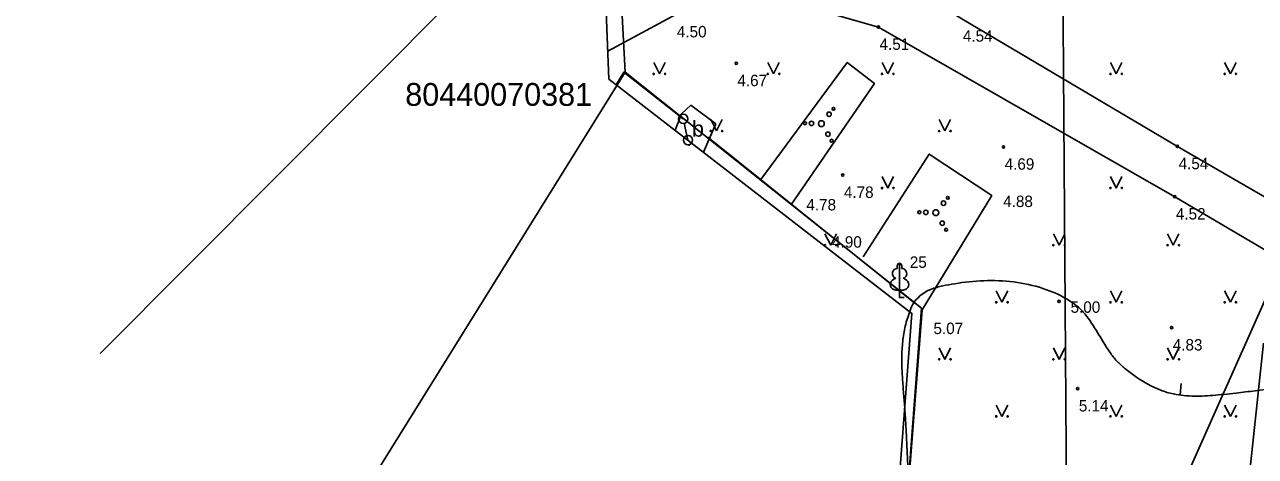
# Model space of a CAD drawing. Extents: x 519536 to 519949, y 326041 to 326519.
# Drawn here: x 519637.2 to 519691.1, y 326168.2 to 326187.2 of the extents above; entities that cross this region are included whole.
import ezdxf

# ---------------------------------------------------------------- set-up
doc = ezdxf.new("R2010")
doc.units = 0
for name, color, linetype in [('CELI_CMAL_####_####_#', 7, 'Continuous'), ('CELI_CSEG_####_TKST_#', 7, 'Continuous'), ('ELEK_VADP_VSPR_####_#', 7, 'Continuous'), ('ELEK_VADV_ZSPR_####_#', 7, 'Continuous'), ('NORB_ELEM_####_####_#', 7, 'Continuous'), ('NORB_ZOGS_BARJ_####_#', 7, 'Continuous'), ('NORB_ZOGS_KBST_####_#', 7, 'Continuous'), ('NORB_ZOGS_ZSTP_####_#', 7, 'Continuous'), ('RAMI_UZMR_####_####_#', 7, 'Continuous'), ('RELJ_AATZ_####_TKST_#', 7, 'Continuous'), ('RELJ_ELEM_####_####_#', 7, 'Continuous'), ('RELJ_HORZ_PAMT_####_#', 7, 'Continuous'), ('ROBZ_UZMR_####_####_#', 7, 'Continuous'), ('ROBZ_UZMR_####_TKST_#', 7, 'Continuous'), ('SILT_VADP_UDEN_####_#', 7, 'Continuous'), ('TERT_DIAM_####_TKST_#', 7, 'Continuous'), ('TERT_ELEM_####_####_#', 7, 'Continuous'), ('TERT_KONT_####_####_#', 7, 'Continuous')]:
    doc.layers.add(name, color=color, linetype=linetype)

msp = doc.modelspace()

# ---------------------------------------------------------------- linework, layer by layer
at = {"layer": 'CELI_CMAL_####_####_#'}
for points in [[(519725.6, 326145.595), (519722.795, 326148.479), (519717.487, 326152.615), (519712.383, 326157.466), (519706.872, 326166.697), (519703.889, 326170.776), (519699.04, 326175.245), (519687.684, 326181.825), (519678.238, 326187.413), (519670.804, 326192.027), (519670.048, 326192.682), (519664.865, 326189.411), (519662.65, 326188.197)], [(519662.737, 326185.995), (519665.714, 326187.6), (519670.496, 326188.216), (519674.588, 326187.052), (519687.563, 326179.623), (519697.361, 326173.852), (519702.298, 326169.28), (519707.151, 326162.302), (519711.634, 326155.197), (519719.91, 326147.956), (519722.688, 326145.028)], [(519665.692, 326182.539), (519665.97, 326183.253)], [(519666.933, 326181.568), (519667.468, 326182.81), (519666.379, 326183.628), (519665.97, 326183.253)], [(519665.688, 326182.529), (519665.692, 326182.539)], [(519666.932, 326181.567), (519666.933, 326181.568)]]:
    msp.add_lwpolyline(points, dxfattribs=at)
at = {"layer": 'ELEK_VADP_VSPR_####_#'}
msp.add_lwpolyline([(519683.028, 326137.518), (519682.623, 326195.513)], dxfattribs=at)
at = {"layer": 'ELEK_VADV_ZSPR_####_#'}
msp.add_line((519666.72, 326119.401), (519722.531, 326244.78), dxfattribs=at)
at = {"layer": 'NORB_ELEM_####_####_#'}
for centre in [(519666.043, 326183.032), (519666.251, 326182.101)]:
    msp.add_circle(centre, 0.202, dxfattribs=at)
at = {"layer": 'NORB_ZOGS_BARJ_####_#'}
for p, q in [((519666.087, 326182.837), (519666.251, 326182.101)), ((519666.295, 326181.906), (519666.309, 326181.844))]:
    msp.add_line(p, q, dxfattribs=at)
at = {"layer": 'NORB_ZOGS_KBST_####_#'}
msp.add_line((519676.196, 326174.948), (519667.128, 326182.232), dxfattribs=at)
for points in [[(519666.043, 326183.032), (519663.443, 326185.082), (519663.124, 326184.549)], [(519663.124, 326184.549), (519663.108, 326184.523)]]:
    msp.add_lwpolyline(points, dxfattribs=at)
at = {"layer": 'NORB_ZOGS_ZSTP_####_#'}
msp.add_lwpolyline([(519659.694, 326134.606), (519659.86, 326134.591), (519673.328, 326133.453), (519674.978, 326154.964), (519676.5, 326174.67)], dxfattribs=at)
at = {"layer": 'RAMI_UZMR_####_####_#'}
msp.add_lwpolyline([(519720.513, 326144.604), (519669.064, 326119.018), (519667.491, 326117.773), (519659.343, 326134.977), (519672.997, 326134.231), (519676.059, 326174.512), (519662.786, 326184.772), (519662.359, 326195.553), (519640.272, 326217.733), (519626.848, 326230.605), (519625.448, 326232.202), (519636.536, 326238.028), (519608.178, 326320.927), (519604.881, 326332.267), (519606.632, 326340.411), (519606.503, 326354.123), (519598.183, 326371.842)], dxfattribs=at)
at = {"layer": 'RELJ_ELEM_####_####_#'}
for centre in [(519674.588, 326187.052), (519668.364, 326185.462), (519680.066, 326181.804), (519687.684, 326181.825), (519673.028, 326180.569), (519687.563, 326179.623), (519682.503, 326175.038), (519687.427, 326173.886), (519683.315, 326171.219)]:
    msp.add_circle(centre, 0.05, dxfattribs=at)
at = {"layer": 'RELJ_HORZ_PAMT_####_#'}
msp.add_line((519687.8, 326170.946), (519687.851, 326171.443), dxfattribs=at)
for points in [[(519679.571, 326197.325), (519680.165, 326196.852), (519680.813, 326196.657), (519682.865, 326196.481), (519684.919, 326196.331), (519689.028, 326196.07), (519690.241, 326196.004), (519691.17, 326195.809), (519691.617, 326195.63), (519692.053, 326195.411), (519692.478, 326195.145), (519692.871, 326194.841), (519693.625, 326194.147), (519694.626, 326192.899), (519695.352, 326191.531), (519696.758, 326187.942), (519697.617, 326185.639), (519698.149, 326184.524), (519698.492, 326183.987), (519698.688, 326183.726), (519698.904, 326183.469), (519699.481, 326182.926), (519699.954, 326182.603), (519700.45, 326182.333), (519701.508, 326181.951), (519702.995, 326181.63), (519704.488, 326181.372), (519706.268, 326181.042), (519708.146, 326180.748), (519709.744, 326180.513), (519711.344, 326180.291), (519712.944, 326180.068), (519714.544, 326179.832), (519716.461, 326179.296), (519716.985, 326179.075)], [(519674.604, 326155.372), (519674.676, 326155.558), (519675.094, 326156.591), (519675.535, 326157.616), (519675.646, 326157.785), (519675.786, 326157.935), (519675.934, 326158.081), (519676.069, 326158.235), (519676.447, 326158.806), (519676.704, 326159.263), (519676.79, 326159.493), (519676.81, 326159.609), (519676.811, 326159.725), (519676.697, 326160.156), (519676.502, 326160.585), (519676.289, 326161.014), (519676.108, 326161.445), (519675.853, 326162.292), (519675.838, 326162.836), (519675.885, 326163.381), (519675.944, 326163.925), (519675.966, 326164.47), (519675.943, 326165.718), (519675.908, 326166.966), (519675.799, 326169.461), (519675.759, 326170.14), (519675.707, 326170.819), (519675.656, 326171.497), (519675.616, 326172.176), (519675.619, 326172.854), (519675.646, 326173.193), (519675.686, 326173.532), (519675.835, 326174.21), (519675.946, 326174.549), (519676.086, 326174.888), (519676.879, 326175.564), (519677.41, 326175.715), (519677.933, 326175.811), (519679.203, 326175.945), (519680.51, 326175.891), (519681.796, 326175.604), (519683, 326175.04), (519683.203, 326174.897), (519683.392, 326174.742), (519683.714, 326174.38), (519684.248, 326173.571), (519684.767, 326172.751), (519685.068, 326172.383), (519685.244, 326172.218), (519685.433, 326172.06), (519686.42, 326171.395), (519686.949, 326171.15), (519687.509, 326170.982), (519687.968, 326170.917), (519688.428, 326170.888), (519689.346, 326170.928), (519690.359, 326171.04)], [(519690.359, 326171.04), (519691.188, 326171.135), (519693.029, 326171.363), (519694.86, 326171.37), (519695.335, 326171.316)]]:
    msp.add_spline(points, degree=3, dxfattribs=at)
at = {"layer": 'ROBZ_UZMR_####_####_#'}
for p, q in [((519662.984, 326195.329), (519640.513, 326172.758)), ((519663.495, 326185.071), (519662.984, 326195.329)), ((519663.495, 326185.071), (519647.84, 326159.889)), ((519676.481, 326174.741), (519663.495, 326185.071)), ((519673.358, 326133.408), (519676.481, 326174.741))]:
    msp.add_line(p, q, dxfattribs=at)
at = {"layer": 'SILT_VADP_UDEN_####_#'}
msp.add_lwpolyline([(519687.958, 326140.524), (519691.454, 326173.209)], dxfattribs=at)
at = {"layer": 'TERT_ELEM_####_####_#'}
for p, q in [((519664.75, 326185.5), (519665, 326185)), ((519665, 326185), (519665.25, 326185.5)), ((519669.75, 326185.5), (519670, 326185)), ((519670, 326185), (519670.25, 326185.5)), ((519674.75, 326185.5), (519675, 326185)), ((519675, 326185), (519675.25, 326185.5)), ((519684.75, 326185.5), (519685, 326185)), ((519685, 326185), (519685.25, 326185.5)), ((519689.75, 326185.5), (519690, 326185)), ((519690, 326185), (519690.25, 326185.5)), ((519667.25, 326183), (519667.5, 326182.5)), ((519667.5, 326182.5), (519667.75, 326183)), ((519677.25, 326183), (519677.5, 326182.5)), ((519677.5, 326182.5), (519677.75, 326183)), ((519674.75, 326180.5), (519675, 326180)), ((519675, 326180), (519675.25, 326180.5)), ((519684.75, 326180.5), (519685, 326180)), ((519685, 326180), (519685.25, 326180.5)), ((519672.25, 326178), (519672.5, 326177.5)), ((519672.5, 326177.5), (519672.75, 326178)), ((519682.25, 326178), (519682.5, 326177.5)), ((519682.5, 326177.5), (519682.75, 326178)), ((519687.25, 326178), (519687.5, 326177.5)), ((519687.5, 326177.5), (519687.75, 326178)), ((519675.514, 326175.554), (519675.514, 326175.207)), ((519675.514, 326175.207), (519675.714, 326175.207)), ((519679.75, 326175.5), (519680, 326175)), ((519680, 326175), (519680.25, 326175.5)), ((519684.75, 326175.5), (519685, 326175)), ((519685, 326175), (519685.25, 326175.5)), ((519689.75, 326175.5), (519690, 326175)), ((519690, 326175), (519690.25, 326175.5)), ((519677.25, 326173), (519677.5, 326172.5)), ((519677.5, 326172.5), (519677.75, 326173)), ((519682.25, 326173), (519682.5, 326172.5)), ((519682.5, 326172.5), (519682.75, 326173)), ((519687.25, 326173), (519687.5, 326172.5)), ((519687.5, 326172.5), (519687.75, 326173)), ((519679.75, 326170.5), (519680, 326170)), ((519680, 326170), (519680.25, 326170.5)), ((519684.75, 326170.5), (519685, 326170)), ((519685, 326170), (519685.25, 326170.5)), ((519689.75, 326170.5), (519690, 326170)), ((519690, 326170), (519690.25, 326170.5))]:
    msp.add_line(p, q, dxfattribs=at)
for points in [[(519675.514, 326176.707), (519675.514, 326175.554)], [(519675.604, 326176.475), (519675.603, 326176.476)]]:
    msp.add_lwpolyline(points, dxfattribs=at)
for centre, radius in [((519664.75, 326185), 0.028), ((519665.25, 326185), 0.0263), ((519669.75, 326185), 0.028), ((519670.25, 326185), 0.0263), ((519674.75, 326185), 0.028), ((519675.25, 326185), 0.0263), ((519684.75, 326185), 0.028), ((519685.25, 326185), 0.0263), ((519689.75, 326185), 0.028), ((519690.25, 326185), 0.0263), ((519672.431, 326183.235), 0.096), ((519672.623, 326183.471), 0.064), ((519671.374, 326182.838), 0.064), ((519671.659, 326182.831), 0.096), ((519672.093, 326182.82), 0.128), ((519667.25, 326182.5), 0.028), ((519667.75, 326182.5), 0.0263), ((519672.379, 326182.359), 0.096), ((519677.25, 326182.5), 0.028), ((519677.75, 326182.5), 0.0263), ((519672.543, 326182.073), 0.064), ((519674.75, 326180), 0.028), ((519675.25, 326180), 0.0263), ((519684.75, 326180), 0.028), ((519685.25, 326180), 0.0263), ((519677.631, 326179.574), 0.064), ((519676.382, 326178.941), 0.064), ((519676.667, 326178.934), 0.096), ((519677.101, 326178.923), 0.128), ((519677.439, 326179.338), 0.096), ((519677.387, 326178.462), 0.096), ((519677.551, 326178.176), 0.064), ((519672.25, 326177.5), 0.028), ((519672.75, 326177.5), 0.0263), ((519682.25, 326177.5), 0.028), ((519682.75, 326177.5), 0.0263), ((519687.25, 326177.5), 0.028), ((519687.75, 326177.5), 0.0263), ((519679.75, 326175), 0.028), ((519680.25, 326175), 0.0263), ((519684.75, 326175), 0.028), ((519685.25, 326175), 0.0263), ((519689.75, 326175), 0.028), ((519690.25, 326175), 0.0263), ((519677.25, 326172.5), 0.028), ((519677.75, 326172.5), 0.0263), ((519682.25, 326172.5), 0.028), ((519682.75, 326172.5), 0.0263), ((519687.25, 326172.5), 0.028), ((519687.75, 326172.5), 0.0263), ((519679.75, 326170), 0.028), ((519680.25, 326170), 0.0263), ((519684.75, 326170), 0.028), ((519685.25, 326170), 0.0263), ((519689.75, 326170), 0.028), ((519690.25, 326170), 0.0263)]:
    msp.add_circle(centre, radius, dxfattribs=at)
for centre, major_axis, ratio, start_param, end_param in [((519675.386, 326176.262), (-0.039, -0.212), 0.861323, 3.141593, 6.283185), ((519675.514, 326176.557), (0, -0.15), 0.707107, 3.14537, 5.287485), ((519675.514, 326176.557), (0, -0.15), 0.707107, 0.995701, 3.137816), ((519675.642, 326176.262), (0.039, -0.212), 0.861323, 0, 3.141593), ((519675.424, 326175.8), (0.307, 0.095), 0.814445, 1.570796, 4.752015), ((519675.604, 326175.8), (-0.307, 0.095), 0.814445, 1.531171, 4.712389)]:
    msp.add_ellipse(centre, major_axis=major_axis, ratio=ratio, start_param=start_param, end_param=end_param, dxfattribs=at)
at = {"layer": 'TERT_KONT_####_####_#'}
for points in [[(519670.78, 326179.299), (519674.417, 326184.582), (519673.228, 326185.504), (519669.443, 326180.372)], [(519676.5, 326174.67), (519679.552, 326179.669), (519676.815, 326181.49), (519673.916, 326176.987)]]:
    msp.add_lwpolyline(points, dxfattribs=at)

# ---------------------------------------------------------------- texts
at = {"layer": 'CELI_CSEG_####_TKST_#'}
msp.add_text('b', height=0.7, dxfattribs=at).set_placement((519666.429, 326182.25))
at = {"layer": 'RELJ_AATZ_####_TKST_#'}
for s, p in [('4.50', (519665.764, 326186.6)), ('4.51', (519674.638, 326186.052)), ('4.54', (519678.288, 326186.413)), ('4.67', (519668.414, 326184.462)), ('4.69', (519680.116, 326180.804)), ('4.54', (519687.734, 326180.825)), ('4.78', (519673.078, 326179.569)), ('4.78', (519671.433, 326179.021)), ('4.88', (519680.052, 326179.169)), ('4.52', (519687.613, 326178.623)), ('4.90', (519672.561, 326177.39)), ('5.00', (519683.003, 326174.538)), ('5.07', (519677, 326173.606)), ('4.83', (519687.477, 326172.886)), ('5.14', (519683.365, 326170.219))]:
    msp.add_text(s, height=0.5, dxfattribs=at).set_placement(p)
at = {"layer": 'ROBZ_UZMR_####_TKST_#'}
msp.add_text('80440070381', height=1, dxfattribs=at).set_placement((519653.872, 326183.601))
at = {"layer": 'TERT_DIAM_####_TKST_#'}
msp.add_text('25      ', height=0.5, dxfattribs=at).set_placement((519675.964, 326176.507))

doc.saveas('drawing.dxf')
